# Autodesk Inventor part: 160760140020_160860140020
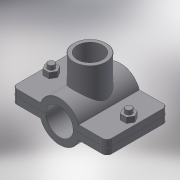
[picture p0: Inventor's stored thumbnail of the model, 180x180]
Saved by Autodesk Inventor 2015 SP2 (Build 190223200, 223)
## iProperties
Created: 2017-05
Part Number: 160760140020_160860140020
Material: Generic
Description: PLASSON SADDLE 140-2"
Document SubType Name: Modeling
Designer: KIM
Density: 1 g/cm^3
Appearance: Default
Author: KIM
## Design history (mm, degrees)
derived "16076.ipt"
feature "Solid1::16076.ipt"
feature "Solid2::16076.ipt"
tag "TaggingFeature1"
body "Solid1"
other parameters: "d0" = 154, "d1" = 201, "d4" = 136, "d5" = 0, "d6" = 10.05, "d7" = 201, "d8" = 0.1, "d10" = 0, "d11" = 1.4, "d14" = 73.6528, "d20" = 1.4, "d23" = 1.4, "d36" = 15, "d37" = 12, "d38" = 78, "d39" = 0, "d40" = 3, "d41" = 5, "d42" = 0, "d44" = 3, "d45" = 0, "d46" = 1.4, "d51" = 112, "d52" = 56.656, "d54" = 0, "d57" = 0, "d58" = 151.2, "d60" = 0, "d62" = 15, "d63" = 12, "d66" = 112, "G_" = 56.656, "A_" = 112, "L_" = 201, "L_1" = 136
